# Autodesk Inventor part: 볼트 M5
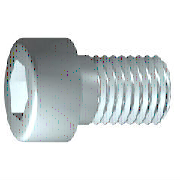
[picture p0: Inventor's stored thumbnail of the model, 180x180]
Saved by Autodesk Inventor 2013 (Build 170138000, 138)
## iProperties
IsCustomPart: 1
Created: 2012-02
Part Number: 볼트 M5
Material: 강철, 연강
Description: 6각머리 태핑 나사
Document SubType Name: Modeling
Standard: KS B 1003
Designer: mduedu
Standards Organization: KS
Language: ko-KR
Size Designation: M 5 x 12
Categories: <MemberInstance><Categories><Category DisplayName="조임쇠" InternalName="e4da775c-781d-43d5-af7c-5136215cf5a6" Mnemonic="FSTN"><Category DisplayName="볼트" InternalN
Density: 1 g/cm^3
Author: mduedu
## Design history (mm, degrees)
sketch "스케치1"
  geometry: L1 (-1.167, 0)-(12, 0); L2 (12, 0)-(12, 2.5); L3 (12, 2.5)-(2, 2.5); L4 (2, 2.5)-(1.509, 2.5); L5 (1.509, 2.5)-(0, 2.5); L6 (0, 2.5)-(0, 4.25); L7 (0, 4.25)-(-5, 4.25); L8 (-5, 4.25)-(-5, 2.309); L9 (-5, 2.309)-(-2.5, 2.309); L10 (-2.5, 2.309)-(-1.167, 0); L11 (-8.4, 0)-(15.4, 0) reference; L12 (0, -0.85)-(0, 5.1) reference; L13 (2, 2.5)-(0, 2.5)
  constraints: 22 end point, 6 parallel, 2 collinear, 2 perpendicular, 1 horizontal, 1 point on line
  dimensions: "d1" = 10 distance from line of L3.end L2 (= GEL); "d2" = 0.49086 distance of L4.end L3.end (computed from GAL); "d3" = 5 distance between parallel lines of L8 L6 (= KOH); "d4" = 2.5 distance of L8.end L9.end (= INTI); "d5" = 60 deg angle of L10 L1; "d6" = 5 diameter of L3 L1 (= GD); "d7" = 5 diameter of L5 L1 (= BDM); "d8" = 4.6188 diameter of L9 L1 (= 1.1547 x SW); "d9" = 8.5 diameter of L7 L1 (= KOD); "d26" = 12 distance between parallel lines of L12 L2 (= NLG)
revolve "본체" sketch "스케치1" stored, may be unused: angle "d10" = 90 deg
sketch "스케치2"
  geometry: L1 (0, -5.95)-(0, 5.95) reference; L2 (-5.95, 0)-(5.95, 0) reference; L3 (2.309, 0)-(1.155, -2); L4 (1.155, -2)-(-1.155, -2); L5 (-1.155, -2)-(-2.309, 0); L6 (-2.309, 0)-(-1.155, 2); L7 (-1.155, 2)-(1.155, 2); L8 (1.155, 2)-(2.309, 0); 2 further points
  constraints: 12 end point, 1 coincident, 1 horizontal alignment, 1 point on line, 12 other
extrude "슬롯" join sketch "스케치2" stored distance "d11" = 10; taper "d12" = 0 deg
workplane "Work Plane1"
fillet "Fillet2" dims "d30" = 0.1 (= R)
body "Solid1"
fillet "모깎기1" dims "d17" = 0.5 (= RR)
feature "스레드" dims "d13" = 10 (= GEL), "d14" = 0
chamfer "모따기1" distance "d15" = 0.49076 (= -0.5 x SPD + 0.5 x GD); stored, may be unused: second distance "d16" = 0.49076 (= GUL), angle "d27" = 45 deg
other parameters: "GD" = 5 (= NND) [user parameter; used in 2 equation terms], "NLG" = 12 [user parameter; used in 1 equation term], "GEL" = 10 [user parameter; used in 2 equation terms], "KOD" = 8.5 [user parameter; used in 1 equation term], "KOH" = 5 [user parameter; used in 1 equation term], "INTI" = 2.5 [user parameter; used in 1 equation term], "GAL" = 0.49076 (= 0.61345 x PTC) [user parameter; used in 1 equation term], "GUL" = 0.49076 (= 0.61345 x PTC) [user parameter; used in 1 equation term], "BDM" = 5 (= NND) [user parameter; used in 1 equation term], "SW" = 4 [user parameter; used in 2 equation terms], "RR" = 0.5 [user parameter; used in 1 equation term], "SPD" = 4.01848 (= NND - 1.2269 x PTC) [user parameter; used in 1 equation term], "d19" = 0, "d28" = 0, "d29" = 0, "R" = 0.1 [user parameter; used in 1 equation term], "PHH" = 0.2 [user parameter], "GD1" = 4.01848 (= THREADDIA - 1.2269 x PTC) [user parameter], "THREADDIA" = 5 [user parameter; used in 1 equation term], "FAWI" = 45 deg [user parameter], "TPU" = 12.5 (computed from PTC) [user parameter], "PTC" = 0.8 [user parameter; used in 5 equation terms], "NND" = 5 [user parameter; used in 3 equation terms], "TOA" = 30 deg [user parameter], "E0" = 4.62 (= 1.155 x SW) [user parameter]
